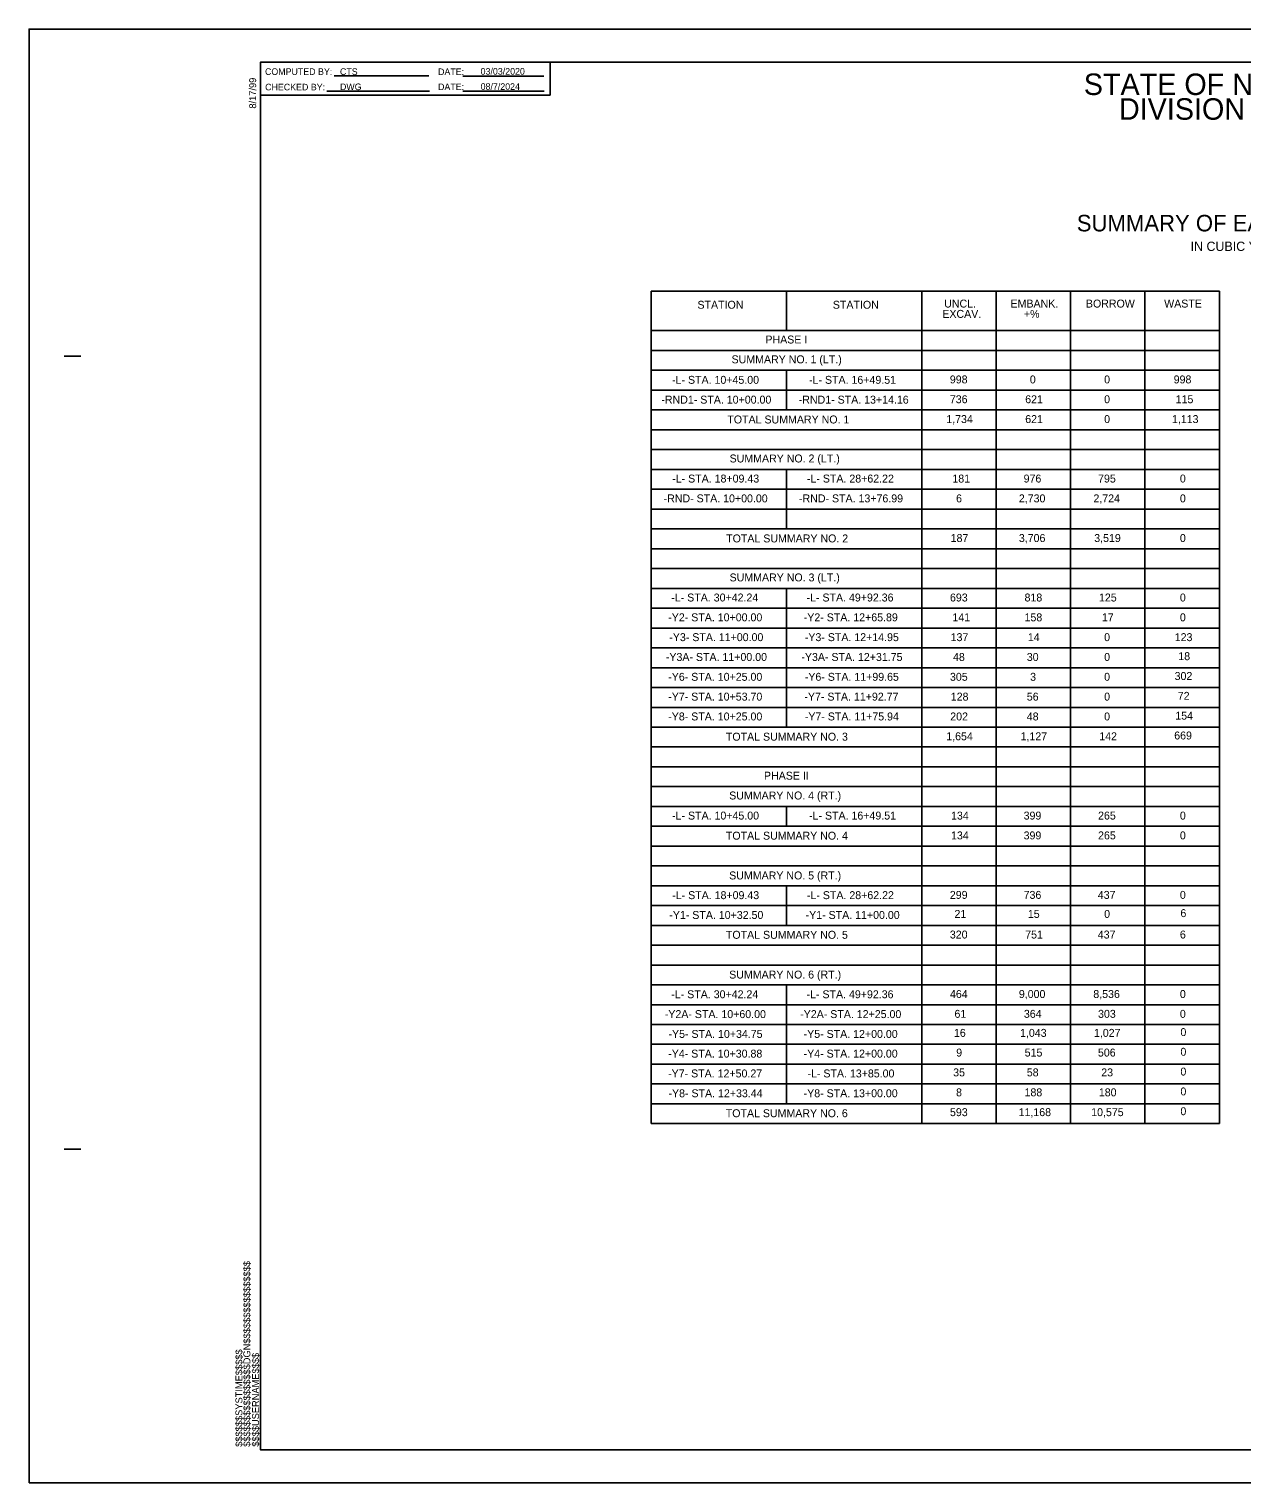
# Model space of a CAD drawing. Extents: x 573680 to 575380, y -53324 to -52224.
# Drawn here: x 573680 to 574597, y -53324 to -52224 of the extents above; entities that cross this region are included whole.
import ezdxf

# ---------------------------------------------------------------- set-up
doc = ezdxf.new("R2010")
doc.units = 0
for name, color, linetype in [('Sheet Block System Information CELL', 7, 'Continuous'), ('Sheet Data Field CELL', 7, 'Continuous'), ('Sheet Plan And Profile CELL', 7, 'Continuous'), ('Sheet Plot Border Outside CELL', 7, 'Continuous'), ('Sheet Summary Combination CELL', 7, 'Continuous'), ('Sheet Summary Combination Grid CELL', 7, 'Continuous')]:
    doc.layers.add(name, color=color, linetype=linetype)

msp = doc.modelspace()

# ---------------------------------------------------------------- linework, layer by layer
at = {"layer": 'Sheet Block System Information CELL'}
msp.add_line((573854.9, -53299.3), (573854.9, -53299.3), dxfattribs=at)
at = {"layer": 'Sheet Plan And Profile CELL'}
for p, q in [((573706.4, -52471.8), (573718.9, -52471.8)), ((573706.4, -53071.8), (573718.9, -53071.8)), ((573854.9, -53299.3), (573854.9, -53299.3)), ((573854.9, -53299.3), (573854.9, -53299.3)), ((573854.9, -53299.3), (573854.9, -53299.3)), ((573854.9, -53299.3), (573854.9, -53299.3)), ((573854.9, -53299.3), (573854.9, -53299.3))]:
    msp.add_line(p, q, dxfattribs=at)
msp.add_lwpolyline([(575354.9, -52249.3), (573854.9, -52249.3), (573854.9, -53299.3), (575354.9, -53299.3)], close=True, dxfattribs=at)
at = {"layer": 'Sheet Plot Border Outside CELL'}
msp.add_lwpolyline([(573679.9, -53324.3), (575379.9, -53324.3), (575379.9, -52224.3), (573679.9, -52224.3)], close=True, dxfattribs=at)
at = {"layer": 'Sheet Summary Combination CELL'}
for p, q in [((573910.5, -52259.7), (573982.1, -52259.7)), ((574007.9, -52259.9), (574069.3, -52259.9)), ((573905.1, -52271.4), (573982.8, -52271.4)), ((574008, -52271.4), (574069.4, -52271.4)), ((574281.5, -52422.5), (574281.5, -52422.5)), ((574289, -52422.7), (574289, -52422.7)), ((574299.9, -52422.4), (574299.9, -52422.4)), ((574306.6, -52422.5), (574306.6, -52422.5))]:
    msp.add_line(p, q, dxfattribs=at)
msp.add_lwpolyline([(573854.9, -52249.3), (574073.9, -52249.3), (574073.9, -52274.3), (573854.9, -52274.3)], close=True, dxfattribs=at)
at = {"layer": 'Sheet Summary Combination Grid CELL'}
for p, q in [((574150.3, -52422.5), (574580.2, -52422.5)), ((574150.3, -52422.5), (574150.3, -52647.5)), ((574252.7, -52422.5), (574252.7, -52452.5)), ((574355.1, -52422.5), (574355.1, -52647.5)), ((574411.4, -52422.5), (574411.4, -52647.5)), ((574467.6, -52422.5), (574467.6, -52647.5)), ((574523.9, -52422.5), (574523.9, -52647.5)), ((574580.2, -52422.5), (574580.2, -52647.5)), ((574150.3, -52452.5), (574580.2, -52452.5)), ((574150.3, -52467.5), (574580.2, -52467.5)), ((574150.3, -52482.5), (574580.2, -52482.5)), ((574252.7, -52482.5), (574252.7, -52512.5)), ((574150.3, -52497.5), (574580.2, -52497.5)), ((574150.3, -52512.5), (574580.2, -52512.5)), ((574150.3, -52527.5), (574580.2, -52527.5)), ((574150.3, -52542.5), (574580.2, -52542.5)), ((574150.3, -52557.5), (574580.2, -52557.5)), ((574252.7, -52557.5), (574252.7, -52602.5)), ((574150.3, -52572.5), (574580.2, -52572.5)), ((574150.3, -52587.5), (574580.2, -52587.5)), ((574150.3, -52602.5), (574580.2, -52602.5)), ((574150.3, -52617.5), (574580.2, -52617.5)), ((574150.3, -52632.5), (574580.2, -52632.5)), ((574150.3, -52647.5), (574150.3, -53052.4)), ((574150.3, -52647.5), (574580.2, -52647.5)), ((574252.7, -52647.5), (574252.7, -52752.5)), ((574355.1, -52647.5), (574355.1, -53052.4)), ((574411.4, -52647.5), (574411.4, -53052.4)), ((574467.6, -52647.5), (574467.6, -53052.4)), ((574523.9, -52647.5), (574523.9, -53052.4)), ((574580.2, -52647.5), (574580.2, -53052.4)), ((574150.3, -52662.5), (574580.2, -52662.5)), ((574150.3, -52677.5), (574580.2, -52677.5)), ((574150.3, -52692.5), (574580.2, -52692.5)), ((574150.3, -52707.5), (574580.2, -52707.5)), ((574150.3, -52722.5), (574580.2, -52722.5)), ((574150.3, -52737.5), (574580.2, -52737.5)), ((574150.3, -52752.5), (574580.2, -52752.5)), ((574150.3, -52767.5), (574580.2, -52767.5)), ((574150.3, -52782.5), (574580.2, -52782.5)), ((574150.3, -52797.5), (574580.2, -52797.5)), ((574150.3, -52812.5), (574580.2, -52812.5)), ((574252.7, -52812.5), (574252.7, -52827.5)), ((574150.3, -52827.5), (574580.2, -52827.5)), ((574150.3, -52842.5), (574580.2, -52842.5)), ((574150.3, -52857.5), (574580.2, -52857.5)), ((574150.3, -52872.5), (574580.2, -52872.5)), ((574252.7, -52872.5), (574252.7, -52902.5)), ((574150.3, -52887.5), (574580.2, -52887.5)), ((574150.3, -52902.5), (574580.2, -52902.5)), ((574150.3, -52917.5), (574580.2, -52917.5)), ((574150.3, -52932.5), (574580.2, -52932.5)), ((574150.3, -52947.5), (574580.2, -52947.5)), ((574252.7, -52947.5), (574252.7, -53037.4)), ((574150.3, -52962.5), (574580.2, -52962.5)), ((574150.3, -52977.5), (574580.2, -52977.5)), ((574150.3, -52992.4), (574580.2, -52992.4)), ((574150.3, -53007.4), (574580.2, -53007.4)), ((574150.3, -53022.4), (574580.2, -53022.4)), ((574150.3, -53037.4), (574580.2, -53037.4)), ((574150.3, -53052.4), (574580.2, -53052.4)), ((574150.3, -53052.4), (574580.2, -53052.4))]:
    msp.add_line(p, q, dxfattribs=at)

# ---------------------------------------------------------------- texts
at = {"layer": 'Sheet Block System Information CELL'}
for s, p in [('$$$$$$$$$$$$$$$$DGN$$$$$$$$$$$$$$$$', (573847.2, -53297)), ('$$$$$$SYSTIME$$$$$', (573841.2, -53297)), ('$$$$USERNAME$$$$', (573853.8, -53296.9))]:
    msp.add_text(s, height=5.25, rotation=90, dxfattribs=at).set_placement(p)
at = {"layer": 'Sheet Data Field CELL'}
for s, p in [('CTS', (573915, -52259)), ('03/03/2020', (574021.4, -52258.8)), ('DWG', (573915, -52270.5)), ('08/7/2024', (574021.4, -52270.3))]:
    msp.add_text(s, height=5, dxfattribs=at).set_placement(p)
at = {"layer": 'Sheet Plan And Profile CELL'}
msp.add_text('8/17/99', height=5.25, rotation=90, dxfattribs=at).set_placement((573851.6, -52284.5))
at = {"layer": 'Sheet Summary Combination CELL'}
for s, height, p in [('COMPUTED BY:', 5, (573858.3, -52259)), ('DATE:', 5, (573989.2, -52259.1)), ('STATE OF NORTH CAROLINA', 16.25, (574477.6, -52274.2)), ('CHECKED BY:', 5, (573858.4, -52270.7)), ('DATE:', 5, (573989.2, -52270.5)), ('DIVISION OF HIGHWAYS', 16.25, (574504.2, -52292.9)), ('STATION', 6, (574185.4, -52435.9)), ('STATION', 6, (574287.8, -52435.9)), ('EXCAV.', 6, (574370.6, -52442.8)), ('UNCL.', 6, (574372, -52435)), ('EMBANK.', 6, (574422.2, -52435)), ('+%', 6, (574432.3, -52442.8)), ('BORROW', 6, (574479.2, -52435)), ('WASTE', 6, (574538.4, -52435)), ('PHASE I', 6, (574236.8, -52462.2)), ('SUMMARY NO. 1 (LT.)', 6, (574211.2, -52477.2)), ('-L- STA. 10+45.00', 6, (574166.2, -52492.7)), ('-L- STA. 16+49.51', 6, (574269.8, -52492.7)), ('998', 6, (574376.3, -52492.4)), ('0', 6, (574436.8, -52492.4)), ('0', 6, (574493, -52492.4)), ('998', 6, (574545.6, -52492.4)), ('-RND1- STA. 10+00.00', 6, (574158.1, -52507.7)), ('-RND1- STA. 13+14.16', 6, (574262, -52507.7)), ('736', 6, (574376.3, -52507.4)), ('621', 6, (574433.3, -52507.4)), ('0', 6, (574493, -52507.4)), ('115', 6, (574547.1, -52507.4)), ('TOTAL SUMMARY NO. 1', 6, (574208, -52522.7)), ('1,734', 6, (574373.6, -52522.4)), ('621', 6, (574433.3, -52522.4)), ('0', 6, (574493, -52522.4)), ('1,113', 6, (574544.3, -52522.4)), ('SUMMARY NO. 2 (LT.)', 6, (574209.7, -52552.2)), ('-L- STA. 18+09.43', 6, (574166.3, -52567.4)), ('-L- STA. 28+62.22', 6, (574268.2, -52567.4)), ('181', 6, (574378.2, -52567.4)), ('976', 6, (574432.1, -52567.4)), ('795', 6, (574488.4, -52567.4)), ('0', 6, (574550.3, -52567.4)), ('-RND- STA. 10+00.00', 6, (574159.8, -52582.4)), ('-RND- STA. 13+76.99', 6, (574262.2, -52582.4)), ('6', 6, (574381, -52582.4)), ('2,730', 6, (574428.5, -52582.4)), ('2,724', 6, (574484.9, -52582.4)), ('0', 6, (574550.3, -52582.4)), ('TOTAL SUMMARY NO. 2', 6, (574207.1, -52612.7)), ('187', 6, (574376.9, -52612.4)), ('3,706', 6, (574428.5, -52612.4)), ('3,519', 6, (574485.5, -52612.4)), ('0', 6, (574550.3, -52612.4)), ('SUMMARY NO. 3 (LT.)', 6, (574209.7, -52642.2)), ('-L- STA. 30+42.24', 6, (574165.6, -52657.4)), ('-L- STA. 49+92.36', 6, (574267.9, -52657.4)), ('693', 6, (574376.4, -52657.4)), ('818', 6, (574432.8, -52657.4)), ('125', 6, (574489.1, -52657.4)), ('0', 6, (574550.3, -52657.4)), ('-Y2- STA. 10+00.00', 6, (574163.3, -52672.4)), ('-Y2- STA. 12+65.89', 6, (574265.8, -52672.4)), ('141', 6, (574378.2, -52672.4)), ('158', 6, (574432.8, -52672.4)), ('17', 6, (574491.3, -52672.4)), ('0', 6, (574550.3, -52672.4)), ('-Y3- STA. 11+00.00', 6, (574164.1, -52687.4)), ('-Y3- STA. 12+14.95', 6, (574266.6, -52687.4)), ('137', 6, (574376.9, -52687.4)), ('14', 6, (574435.3, -52687.4)), ('0', 6, (574493, -52687.4)), ('123', 6, (574546.4, -52687.4)), ('-Y3A- STA. 11+00.00', 6, (574161.5, -52702.4)), ('-Y3A- STA. 12+31.75', 6, (574264, -52702.4)), ('48', 6, (574378.7, -52702.4)), ('30', 6, (574434.5, -52702.4)), ('0', 6, (574493, -52702.4)), ('18', 6, (574549.1, -52701.8)), ('-Y6- STA. 10+25.00', 6, (574163.3, -52717.4)), ('-Y6- STA. 11+99.65', 6, (574266.6, -52717.4)), ('305', 6, (574376.4, -52717.4)), ('3', 6, (574437, -52717.4)), ('0', 6, (574493, -52717.4)), ('302', 6, (574546.3, -52716.8)), ('-Y7- STA. 10+53.70', 6, (574163.3, -52732.4)), ('-Y7- STA. 11+92.77', 6, (574266.3, -52732.4)), ('128', 6, (574377, -52732.4)), ('56', 6, (574434.5, -52732.4)), ('0', 6, (574493, -52732.4)), ('72', 6, (574548.7, -52731.8)), ('-Y8- STA. 10+25.00', 6, (574163.3, -52747.4)), ('-Y7- STA. 11+75.94', 6, (574266.6, -52747.4)), ('202', 6, (574376.6, -52747.4)), ('48', 6, (574434.5, -52747.4)), ('0', 6, (574493, -52747.4)), ('154', 6, (574546.8, -52746.8)), ('669', 6, (574546, -52761.8)), ('TOTAL SUMMARY NO. 3', 6, (574206.9, -52762.7)), ('1,654', 6, (574373.6, -52762.4)), ('1,127', 6, (574429.8, -52762.4)), ('142', 6, (574489.3, -52762.4)), ('PHASE II', 6, (574235.7, -52792.2)), ('SUMMARY NO. 4 (RT.)', 6, (574209.4, -52807.2)), ('-L- STA. 10+45.00', 6, (574166.2, -52822.4)), ('-L- STA. 16+49.51', 6, (574269.8, -52822.4)), ('134', 6, (574377.2, -52822.4)), ('399', 6, (574432.1, -52822.4)), ('265', 6, (574488.4, -52822.4)), ('0', 6, (574550.3, -52822.4)), ('TOTAL SUMMARY NO. 4', 6, (574206.9, -52837.6)), ('134', 6, (574377.2, -52837.4)), ('399', 6, (574432.1, -52837.4)), ('265', 6, (574488.4, -52837.4)), ('0', 6, (574550.3, -52837.4)), ('SUMMARY NO. 5 (RT.)', 6, (574209.4, -52867.7)), ('-L- STA. 18+09.43', 6, (574166.3, -52882.6)), ('-L- STA. 28+62.22', 6, (574268.2, -52882.6)), ('299', 6, (574376.3, -52882.4)), ('736', 6, (574432.1, -52882.4)), ('437', 6, (574488.2, -52882.4)), ('0', 6, (574550.3, -52882.4)), ('-Y1- STA. 10+32.50', 6, (574164.1, -52897.6)), ('-Y1- STA. 11+00.00', 6, (574267.2, -52897.6)), ('21', 6, (574379.8, -52896.8)), ('15', 6, (574435.3, -52896.8)), ('0', 6, (574493, -52896.8)), ('6', 6, (574550.7, -52896.2)), ('TOTAL SUMMARY NO. 5', 6, (574206.9, -52912.6)), ('320', 6, (574376.3, -52912.4)), ('751', 6, (574433.3, -52912.4)), ('437', 6, (574488.2, -52912.4)), ('6', 6, (574550.3, -52912.4)), ('SUMMARY NO. 6 (RT.)', 6, (574209.4, -52942.7)), ('-L- STA. 30+42.24', 6, (574165.6, -52957.6)), ('-L- STA. 49+92.36', 6, (574267.9, -52957.6)), ('464', 6, (574376.4, -52957.4)), ('9,000', 6, (574428.5, -52957.4)), ('8,536', 6, (574484.8, -52957.4)), ('0', 6, (574550.3, -52957.4)), ('-Y2A- STA. 10+60.00', 6, (574160.7, -52972.6)), ('-Y2A- STA. 12+25.00', 6, (574263.1, -52972.6)), ('61', 6, (574379.8, -52972.4)), ('364', 6, (574432.3, -52972.4)), ('303', 6, (574488.4, -52972.4)), ('0', 6, (574550.3, -52972.4)), ('-Y5- STA. 10+34.75', 6, (574163.5, -52987.6)), ('-Y5- STA. 12+00.00', 6, (574265.7, -52987.6)), ('16', 6, (574379.4, -52986.8)), ('1,043', 6, (574429.4, -52986.8)), ('1,027', 6, (574485.3, -52986.8)), ('0', 6, (574550.7, -52986.2)), ('-Y4- STA. 10+30.88', 6, (574163.3, -53002.5)), ('-Y4- STA. 12+00.00', 6, (574265.7, -53002.5)), ('9', 6, (574381.1, -53001.7)), ('515', 6, (574432.9, -53001.7)), ('506', 6, (574488.3, -53001.7)), ('0', 6, (574550.7, -53001.1)), ('-Y7- STA. 12+50.27', 6, (574163.2, -53017.5)), ('-L- STA. 13+85.00', 6, (574268.6, -53017.5)), ('35', 6, (574378.8, -53016.7)), ('58', 6, (574434.5, -53016.7)), ('23', 6, (574490.8, -53016.7)), ('0', 6, (574550.7, -53016.1)), ('-Y8- STA. 12+33.44', 6, (574163.5, -53032.5)), ('-Y8- STA. 13+00.00', 6, (574265.7, -53032.5)), ('8', 6, (574381, -53031.8)), ('188', 6, (574432.8, -53031.8)), ('180', 6, (574489, -53031.8)), ('0', 6, (574550.7, -53031.1)), ('TOTAL SUMMARY NO. 6', 6, (574206.8, -53047.6)), ('593', 6, (574376.4, -53046.8)), ('11,168', 6, (574428.3, -53046.8)), ('10,575', 6, (574483.2, -53046.8)), ('0', 6, (574550.7, -53046.1))]:
    msp.add_text(s, height=height, dxfattribs=at).set_placement(p)
for s, height, p in [('SUMMARY OF EARTHWORK', 12.5, (574472.3, -52377.4)), ('IN CUBIC YARDS', 7.031, (574558.4, -52392.2))]:
    msp.add_text(s, height=height, rotation=0.0119, dxfattribs=at).set_placement(p)

doc.saveas('drawing.dxf')
